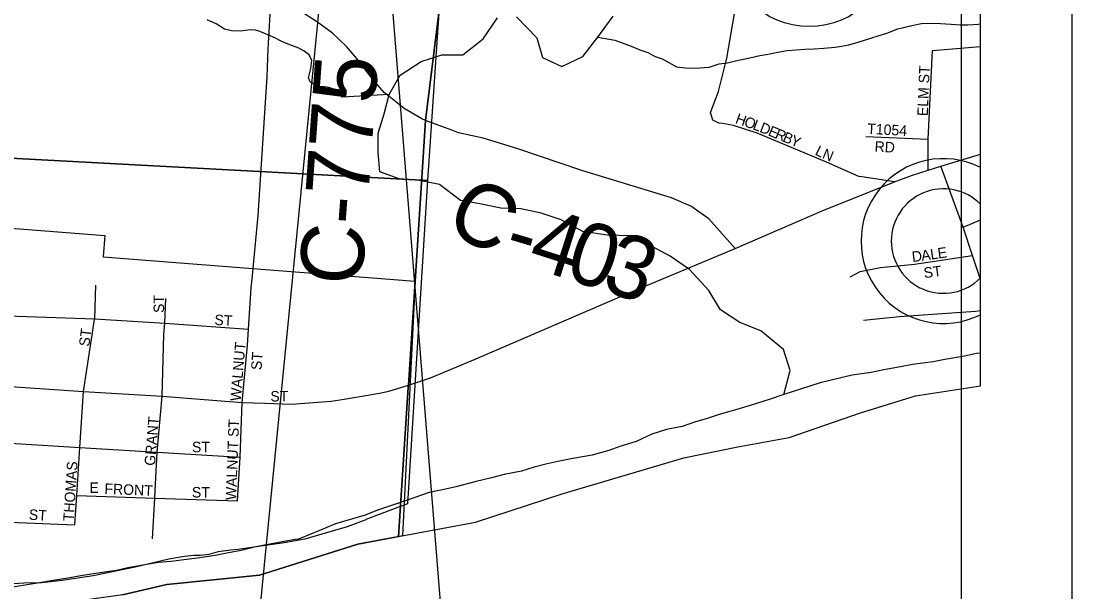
# Model space of a CAD drawing. Extents: x 0 to 34, y 0 to 22.
# Drawn here: x 8.552 to 9.5, y 16.434 to 16.95 of the extents above; entities that cross this region are included whole.
import ezdxf

# ---------------------------------------------------------------- set-up
doc = ezdxf.new("R2010")
doc.units = 0
for name, color, linetype in [('GM_X_City_Street', 7, 'Continuous'), ('GM_X_City_Street_Text', 7, 'Continuous'), ('GM_X_Corporation', 7, 'Continuous'), ('GM_X_County', 7, 'Continuous'), ('GM_X_County_Road', 7, 'Continuous'), ('GM_X_County_Road_Text', 7, 'Continuous'), ('GM_X_Major_River', 7, 'Continuous'), ('GM_X_Minor_River', 7, 'Continuous'), ('GM_X_Section', 7, 'Continuous'), ('GM_X_Township', 7, 'Continuous'), ('GM_X_Township_Subdivision', 7, 'Continuous'), ('GM_X_Township_Subdivision_Text', 7, 'Continuous'), ('GM_X_Unincorporated', 7, 'Continuous'), ('GM_X_Unincorporated_Location', 7, 'Continuous'), ('SH_Data', 7, 'Continuous'), ('SH_Text', 7, 'Continuous')]:
    doc.layers.add(name, color=color, linetype=linetype)

msp = doc.modelspace()

# ---------------------------------------------------------------- linework, layer by layer
at = {"layer": 'GM_X_City_Street'}
for points in [[(8.75106, 16.60504), (8.75581, 16.65688), (8.7568, 16.6712), (8.75927, 16.70872), (8.76006, 16.71683)], [(8.61801, 16.68013), (8.61808, 16.68057), (8.61907, 16.71118)], [(8.68049, 16.66655), (8.68049, 16.66656), (8.68126, 16.67663), (8.68231, 16.69908)], [(8.47677, 16.68539), (8.61808, 16.68057), (8.68126, 16.67663), (8.7568, 16.6712)], [(8.6001, 16.49473), (8.60182, 16.52121), (8.60464, 16.56456), (8.60794, 16.61507), (8.61801, 16.68013)], [(8.67265, 16.52559), (8.67458, 16.56028), (8.6788, 16.61072), (8.68049, 16.66655)], [(8.34929, 16.65375), (8.38843, 16.64458), (8.41941, 16.63711), (8.45225, 16.62974), (8.47345, 16.62483), (8.49424, 16.62289), (8.51978, 16.62123), (8.60794, 16.61507), (8.6788, 16.61072), (8.75106, 16.60504)], [(8.77156, 16.60444), (8.79574, 16.60374), (8.83152, 16.60639), (8.84305, 16.60827)], [(8.84305, 16.60827), (8.87511, 16.6135), (8.88088, 16.61463), (8.8834, 16.6154)], [(8.74694, 16.51627), (8.74925, 16.55571), (8.75106, 16.60504)], [(8.75106, 16.60504), (8.77156, 16.60444)], [(8.4497, 16.57405), (8.60464, 16.56456), (8.67458, 16.56028), (8.74925, 16.55571)], [(8.67023, 16.4822), (8.67227, 16.51881), (8.67265, 16.52557), (8.67265, 16.52559)], [(8.60182, 16.52121), (8.67227, 16.51881), (8.74694, 16.51627)], [(8.44635, 16.501), (8.6001, 16.49473)]]:
    msp.add_lwpolyline(points, dxfattribs=at)
at = {"layer": 'GM_X_Corporation'}
msp.add_lwpolyline([(8.23601, 16.40147), (8.27095, 16.87558), (8.46775, 16.80018), (8.46651, 16.78413), (8.51245, 16.78054), (8.51125, 16.76503), (8.6273, 16.75596), (8.62582, 16.73673), (8.90737, 16.71471), (8.89569, 16.48465), (8.85558, 16.47717), (8.76686, 16.44926), (8.68303, 16.44075), (8.64321, 16.43155), (8.58366, 16.42308), (8.52372, 16.42146), (8.50098, 16.41001), (8.47331, 16.3978), (8.42018, 16.40341), (8.40651, 16.41099), (8.3439, 16.41278), (8.29722, 16.41954), (8.27221, 16.40391)], close=True, dxfattribs=at)
at = {"layer": 'GM_X_County'}
for points in [[(9.41749, 16.62026), (9.41749, 20.9), (2.61749, 20.9), (2.61749, 15.16941)], [(8.64321, 16.43155), (8.68303, 16.44075), (8.76686, 16.44926), (8.85558, 16.47717), (8.89235, 16.48403), (8.96179, 16.49697), (9.0399, 16.52274), (9.14986, 16.55533), (9.19839, 16.56517), (9.24465, 16.57348), (9.30911, 16.59585), (9.35879, 16.61101), (9.41749, 16.62026)]]:
    msp.add_lwpolyline(points, dxfattribs=at)
at = {"layer": 'GM_X_County_Road'}
for points in [[(8.76006, 16.71683), (8.76568, 16.77388), (8.77358, 16.89927), (8.77457, 16.92445), (8.77727, 16.97112)], [(8.94037, 16.85084), (8.91659, 16.8597), (8.91318, 16.86132), (8.89722, 16.87058), (8.87941, 16.88492), (8.8697, 16.89603), (8.85443, 16.91593), (8.84518, 16.92657), (8.83269, 16.9386), (8.81812, 16.94901), (8.804, 16.95803), (8.79175, 16.96429), (8.77727, 16.97112), (8.77236, 16.97343)], [(9.19606, 16.74413), (9.17215, 16.77083), (9.15617, 16.78237), (9.13847, 16.78979), (9.0585, 16.81433), (8.99902, 16.83431), (8.96859, 16.84371), (8.94635, 16.84861), (8.94037, 16.85084)], [(8.8834, 16.6154), (8.90117, 16.62078), (8.92096, 16.62753), (8.96151, 16.64434), (9.10047, 16.70404), (9.19606, 16.74413), (9.27447, 16.77802), (9.33977, 16.80438), (9.3551, 16.81007), (9.37012, 16.81491), (9.3816, 16.81862), (9.41749, 16.82921)]]:
    msp.add_lwpolyline(points, dxfattribs=at)
at = {"layer": 'GM_X_Major_River'}
for points in [[(9.41749, 16.64969), (9.41392, 16.64934), (9.40297, 16.64701), (9.38522, 16.64388), (9.37465, 16.64193), (9.35614, 16.63956), (9.34519, 16.63723), (9.33009, 16.6345), (9.31876, 16.63217), (9.30176, 16.62981), (9.29006, 16.62709), (9.27269, 16.62283), (9.25496, 16.61705), (9.23986, 16.61242), (9.22665, 16.6078), (9.20967, 16.60239), (9.19759, 16.59892), (9.18174, 16.59428), (9.17079, 16.59081), (9.15947, 16.58734), (9.14815, 16.58348), (9.13418, 16.58076), (9.12097, 16.57652), (9.10664, 16.56999), (9.09192, 16.56536), (9.08211, 16.56189), (9.06701, 16.55764), (9.04964, 16.55452), (9.03604, 16.5518), (9.02509, 16.54946), (9.01452, 16.54675), (9.0032, 16.54328), (8.98772, 16.54017), (8.97602, 16.53707), (8.96243, 16.53397), (8.94393, 16.52894), (8.93185, 16.52622), (8.91976, 16.52388), (8.9009, 16.51734), (8.88693, 16.51233), (8.87335, 16.50809), (8.86203, 16.50348), (8.83523, 16.49575), (8.82542, 16.49152), (8.802, 16.48187)], [(8.802, 16.48187), (8.7989, 16.48142), (8.78755, 16.47949), (8.77621, 16.47718), (8.76335, 16.47487), (8.75011, 16.47141), (8.73725, 16.46909), (8.72665, 16.46717), (8.71303, 16.46485), (8.70093, 16.4633), (8.68693, 16.46174), (8.67558, 16.46057), (8.66158, 16.45825), (8.64796, 16.45594), (8.63775, 16.45363), (8.62488, 16.4517), (8.60748, 16.44899), (8.59386, 16.44667), (8.58062, 16.44436), (8.56813, 16.44242)], [(8.56813, 16.44242), (8.55716, 16.44049), (8.5443, 16.43856)]]:
    msp.add_lwpolyline(points, dxfattribs=at)
at = {"layer": 'GM_X_Minor_River'}
for points in [[(8.8834, 16.88307), (8.88378, 16.88319), (8.84134, 16.88066), (8.83838, 16.8849), (8.83389, 16.88802), (8.82937, 16.88962), (8.82559, 16.89006), (8.82143, 16.89013), (8.81616, 16.89212), (8.81241, 16.89447), (8.81096, 16.8983), (8.813, 16.90664), (8.81388, 16.91385), (8.81169, 16.91884), (8.80721, 16.92234), (8.80233, 16.92509), (8.79405, 16.92789), (8.78691, 16.93105), (8.78015, 16.93459), (8.76699, 16.94015), (8.76322, 16.94135), (8.7583, 16.94144), (8.74957, 16.94044), (8.74162, 16.94058), (8.73521, 16.94221), (8.72771, 16.9469), (8.71944, 16.95047)], [(9.23986, 16.61242), (9.24568, 16.63401), (9.23961, 16.65301), (9.21917, 16.66973), (9.20025, 16.67732), (9.18283, 16.68872), (9.17223, 16.7062), (9.15481, 16.7252), (9.1374, 16.73735), (9.11999, 16.74647), (9.10182, 16.75558), (9.08062, 16.75633), (9.05867, 16.75936), (9.03899, 16.76999), (9.02082, 16.77606), (9.00265, 16.77986), (8.98448, 16.78061), (8.96556, 16.7844), (8.94815, 16.78743), (8.92922, 16.80187), (8.91105, 16.80566), (8.89289, 16.80717), (8.87547, 16.81324), (8.87396, 16.83073), (8.87395, 16.84821), (8.87925, 16.8657), (8.88378, 16.88319), (8.89362, 16.90067), (8.91254, 16.91285), (8.93146, 16.91894), (8.95039, 16.91895), (8.96855, 16.9334), (8.98142, 16.95241)], [(8.99883, 16.95318), (9.017, 16.93419), (9.0223, 16.91671), (9.03971, 16.90835), (9.05863, 16.91748), (9.07225, 16.93498), (9.08588, 16.95398)], [(9.07225, 16.93498), (9.08734, 16.93214), (9.10208, 16.92696), (9.11, 16.92341), (9.11718, 16.92102), (9.12397, 16.91748), (9.13002, 16.91549), (9.13604, 16.91196), (9.1432, 16.90804), (9.15116, 16.90716), (9.15686, 16.90707), (9.16408, 16.90734), (9.17245, 16.90798), (9.18161, 16.91088), (9.18923, 16.91191), (9.19647, 16.9137), (9.20218, 16.91476), (9.20943, 16.91617), (9.21819, 16.91832), (9.22391, 16.91938), (9.23458, 16.9215), (9.24296, 16.9229), (9.25932, 16.92417), (9.2673, 16.92443), (9.27604, 16.92506), (9.28632, 16.92604), (9.29202, 16.92671), (9.2985, 16.92814), (9.30804, 16.93066), (9.31835, 16.93393), (9.32598, 16.93648), (9.33286, 16.93866), (9.34279, 16.94232), (9.35538, 16.94555), (9.36414, 16.94733), (9.37668, 16.94751), (9.3911, 16.94653), (9.39907, 16.94602), (9.40591, 16.94592), (9.41542, 16.94654), (9.41749, 16.94699)]]:
    msp.add_lwpolyline(points, dxfattribs=at)
at = {"layer": 'GM_X_Section'}
msp.add_lwpolyline([(7.90779, 17.87153), (8.98573, 17.80947), (8.96369, 17.47789), (8.91849, 16.80562), (7.83957, 16.86322)], close=True, dxfattribs=at)
msp.add_lwpolyline([(7.83957, 16.86322), (8.91849, 16.80562), (8.9004, 16.5136), (8.86289, 16.49943), (8.86268, 16.49935), (8.84583, 16.49303), (8.8231, 16.4862), (8.80757, 16.48164), (8.789, 16.4786), (8.74733, 16.4725), (8.74089, 16.47174), (8.72952, 16.47021), (8.72119, 16.46793), (8.71361, 16.46717), (8.70793, 16.46716), (8.69921, 16.46602), (8.68481, 16.46374), (8.65451, 16.45651), (8.61663, 16.44853), (8.58859, 16.44434), (8.57003, 16.44243), (8.55411, 16.44204), (8.54047, 16.44127)], dxfattribs=at)
at = {"layer": 'GM_X_Township'}
for points in [[(9.41749, 16.62026), (9.41749, 20.9), (9.19495, 20.9)], [(8.64321, 16.43155), (8.68303, 16.44075), (8.76686, 16.44926), (8.85558, 16.47717), (8.89235, 16.48403), (8.90103, 16.6186), (8.90117, 16.62078), (8.91659, 16.8597), (8.93623, 17.01787), (8.9323, 17.07979), (8.93495, 17.1194), (8.94107, 17.16829), (8.94295, 17.23892), (8.94748, 17.31225), (8.95015, 17.35542), (8.95521, 17.43732), (9.00565, 18.22153), (9.00736, 18.24811), (9.02237, 18.49878), (9.08108, 19.18441)], [(9.08108, 19.18441), (9.02237, 18.49878), (9.00736, 18.24811), (9.00565, 18.22153), (8.95521, 17.43732), (8.95015, 17.35542), (8.94748, 17.31225), (8.94295, 17.23892), (8.94107, 17.16829), (8.93495, 17.1194), (8.9323, 17.07979), (8.93623, 17.01787), (8.91659, 16.8597), (8.90117, 16.62078), (8.90103, 16.6186), (8.89235, 16.48403), (8.96179, 16.49697), (9.0399, 16.52274), (9.14986, 16.55533), (9.19839, 16.56517), (9.24465, 16.57348), (9.30911, 16.59585), (9.35879, 16.61101), (9.41749, 16.62026)]]:
    msp.add_lwpolyline(points, dxfattribs=at)
at = {"layer": 'GM_X_Township_Subdivision'}
for points in [[(9.18495, 16.90148), (9.1853, 16.90288), (9.18852, 16.91604), (9.19855, 16.97389), (9.20237, 16.99592), (9.20696, 17.02061), (9.21736, 17.07656)], [(9.37012, 16.81491), (9.3701, 16.84276), (9.37416, 16.92284)], [(9.37416, 16.92284), (9.41749, 16.92647)], [(9.1812, 16.85744), (9.18096, 16.85746), (9.17998, 16.85799), (9.17602, 16.86009), (9.1737, 16.86691), (9.18115, 16.88596), (9.18495, 16.90148)], [(9.31043, 16.80885), (9.30756, 16.80928), (9.27858, 16.82204), (9.21589, 16.8482), (9.19462, 16.85527), (9.18476, 16.85711), (9.1812, 16.85744)], [(9.31386, 16.84518), (9.3701, 16.84276)], [(9.41749, 16.71615), (9.41019, 16.73793), (9.40167, 16.76336), (9.3816, 16.81862)], [(9.33977, 16.80438), (9.31043, 16.80885)], [(9.40167, 16.76336), (9.41749, 16.76991)], [(9.29991, 16.71858), (9.30899, 16.72354), (9.32717, 16.727), (9.35784, 16.73009), (9.41019, 16.73793)], [(9.31171, 16.67944), (9.34427, 16.68292), (9.41282, 16.6876), (9.41749, 16.68809)]]:
    msp.add_lwpolyline(points, dxfattribs=at)
at = {"layer": 'GM_X_Unincorporated'}
for p, q in [((9.41749, 16.68441), (9.41749, 16.81737)), ((9.41749, 16.7176), (9.41749, 16.78418))]:
    msp.add_line(p, q, dxfattribs=at)
msp.add_circle((9.26282, 17.01885), 0.0744, dxfattribs=at)
for radius, start, end in [(0.0744, 63.31535, 296.68465), (0.04716, 44.89216, 315.10784)]:
    msp.add_arc((9.38408, 16.75089), radius, start, end, dxfattribs=at)
at = {"layer": 'GM_X_Unincorporated_Location'}
msp.add_line((9.38408, 16.75089), (9.38408, 16.75089), dxfattribs=at)
at = {"layer": 'SH_Data'}
for p, q in [((9.5, 21), (9.5, 14)), ((9.4, 20.9), (9.4, 14.1))]:
    msp.add_line(p, q, dxfattribs=at)
at = {"layer": 'SH_Text'}
msp.add_lwpolyline([(9.02903, 15.19549), (8.857, 17.33375), (8.64678, 15.19549)], close=True, dxfattribs=at)

# ---------------------------------------------------------------- texts
at = {"layer": 'GM_X_City_Street_Text'}
for s, rotation, p in [('ST', 90, (8.68067, 16.68594)), ('ST', 356.42452, (8.72589, 16.67522)), ('ST', 82.87886, (8.61318, 16.65532)), ('WALNUT', 85.23897, (8.74983, 16.60608)), ('ST', 86.42562, (8.76859, 16.6342)), ('ST', 0.00001, (8.77661, 16.60605)), ('GRANT', 85.23444, (8.67234, 16.54775)), ('WALNUT ST', 87.85463, (8.74566, 16.51686)), ('ST', 0.00001, (8.70578, 16.56022)), ('THOMAS', 86.12359, (8.59901, 16.49772)), ('E', 0.00001, (8.61328, 16.52355)), ('FRONT', 357.51071, (8.62669, 16.52272)), ('ST', 0.00001, (8.70578, 16.51938)), ('ST', 356.42452, (8.55839, 16.49938))]:
    msp.add_text(s, height=0.00947, rotation=rotation, dxfattribs=at).set_placement(p)
at = {"layer": 'GM_X_County_Road_Text'}
for s, height, rotation, p in [('C-775', 0.056818, 85.87273, (8.85913, 16.70989)), ('C', 0.05682, 331.09978, (8.93194, 16.76267)), ('4', 0.05682, 342.2272, (9.00711, 16.7284)), ('0', 0.05682, 342.22659, (9.04044, 16.71771)), ('-', 0.05682, 343.38425, (8.98504, 16.73498)), ('3', 0.05682, 341.85243, (9.07367, 16.70706))]:
    msp.add_text(s, height=height, rotation=rotation, dxfattribs=at).set_placement(p)
at = {"layer": 'GM_X_Township_Subdivision_Text'}
for s, rotation, p in [('ELM ST', 87.66398, (9.36983, 16.86351)), ('H', 340.16791, (9.19555, 16.85761)), ('O', 340.16791, (9.20339, 16.85479)), ('L', 339.44396, (9.2112, 16.85197)), ('D', 337.89119, (9.21738, 16.84965)), ('E', 337.55039, (9.22509, 16.84652)), ('T1054', 356.82034, (9.31504, 16.84769)), ('R', 337.55299, (9.23125, 16.84397)), ('B', 337.56506, (9.23818, 16.84111)), ('Y', 337.55582, (9.24511, 16.83825)), ('L', 333.96656, (9.26743, 16.82918)), ('RD', 356.98759, (9.32169, 16.83162)), ('N', 337.26425, (9.27395, 16.82602)), ('D', 6.85666, (9.35608, 16.7319)), ('A', 8.10201, (9.36458, 16.73293)), ('L', 8.13166, (9.37283, 16.7341)), ('E', 8.13332, (9.37943, 16.73504)), ('ST', 7.12502, (9.36675, 16.71737))]:
    msp.add_text(s, height=0.00947, rotation=rotation, dxfattribs=at).set_placement(p)

doc.saveas('drawing.dxf')
